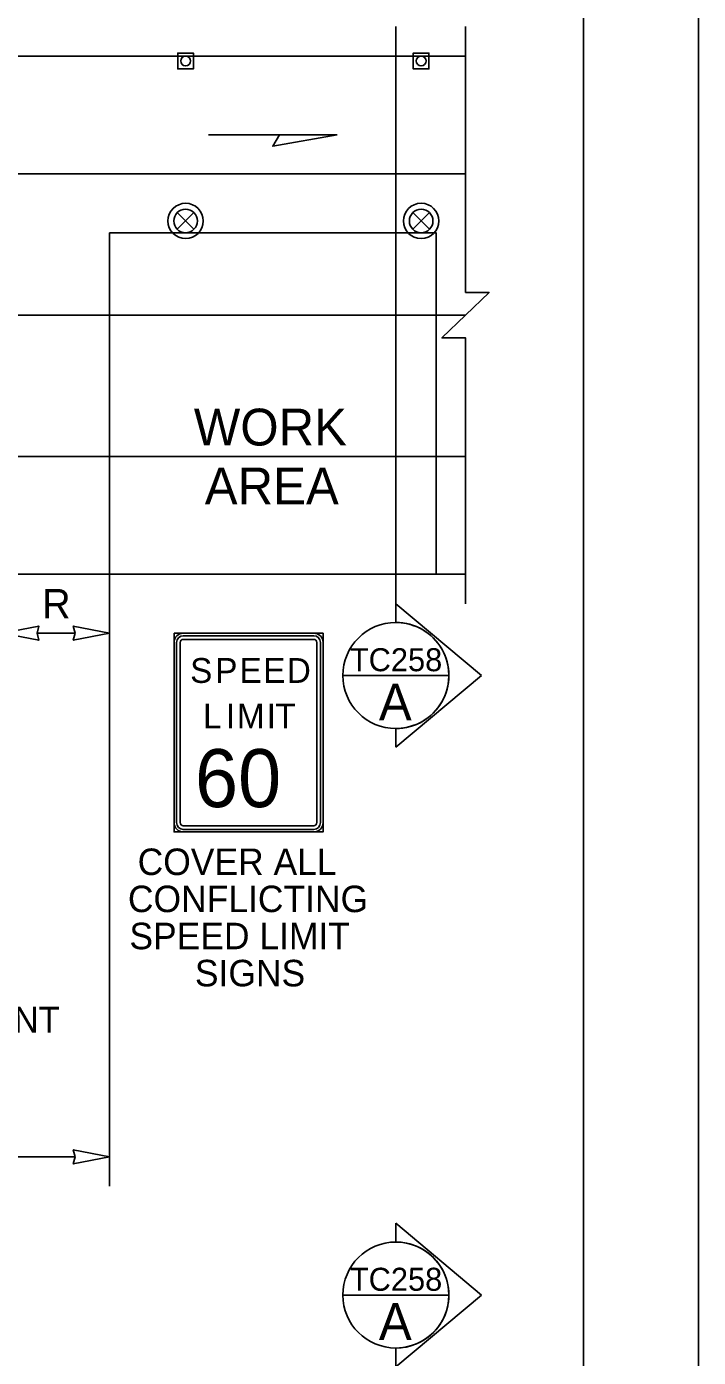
# Model space of a CAD drawing. Extents: x 99999 to 100116, y 99995 to 100013.
# Drawn here: x 100054.238 to 100056.062, y 100004.663 to 100008.279 of the extents above; entities that cross this region are included whole.
import ezdxf

# ---------------------------------------------------------------- set-up
doc = ezdxf.new("R2010")
doc.units = 0
for name, color, linetype in [('RD_MK_LineEdgeYellow', 7, 'Continuous'), ('RD_MK_LineLane', 7, 'Continuous'), ('SH_GI_PlotLimits', 7, 'Continuous'), ('SH_GI_SectionCut', 7, 'Continuous'), ('SH_GI_SheetBorder', 7, 'Continuous'), ('TR_SN_ConstructionSigns', 7, 'Continuous'), ('TR_WZ_TrafficCone', 7, 'Continuous'), ('TR_WZ_TrafficSafetyDrum', 7, 'Continuous'), ('TR_WZ_WorkAreaLabel', 7, 'Continuous'), ('TR_WZ_WorkZoneDetails', 7, 'Continuous'), ('TR_WZ_WorkZoneTextCurrent', 7, 'Continuous')]:
    doc.layers.add(name, color=color, linetype=linetype)

msp = doc.modelspace()

# ---------------------------------------------------------------- linework, layer by layer
at = {"layer": 'RD_MK_LineEdgeYellow'}
for p, q in [((100048.195, 100007.8789), (100055.43, 100007.8789)), ((100052.7368, 100007.1109), (100055.43, 100007.1109))]:
    msp.add_line(p, q, dxfattribs=at)
at = {"layer": 'RD_MK_LineLane'}
msp.add_lwpolyline([(100055.43, 100007.4949), (100048.195, 100007.4949)], dxfattribs=at)
at = {"layer": 'SH_GI_PlotLimits'}
msp.add_lwpolyline([(100039.0625, 99999.6875), (100056.0625, 99999.6875), (100056.0625, 100010.6875), (100039.0625, 100010.6875)], close=True, dxfattribs=at)
at = {"layer": 'SH_GI_SectionCut'}
for p, q in [((100055.2407, 100006.7109), (100055.2407, 100008.2789)), ((100055.2407, 100006.7109), (100055.2407, 100006.66)), ((100055.4733, 100006.516), (100055.2407, 100006.7109)), ((100055.2407, 100006.3211), (100055.4733, 100006.516)), ((100055.2407, 100006.372), (100055.2407, 100006.3211)), ((100055.2407, 100004.9768), (100055.2407, 100005.0277)), ((100055.2407, 100005.0277), (100055.4733, 100004.8328)), ((100055.4733, 100004.8328), (100055.2407, 100004.638)), ((100055.2407, 100004.638), (100055.2407, 100004.6888))]:
    msp.add_line(p, q, dxfattribs=at)
for points in [[(100055.0967, 100006.516), (100055.3847, 100006.516)], [(100055.0967, 100004.8328), (100055.3847, 100004.8328)]]:
    msp.add_lwpolyline(points, dxfattribs=at)
for centre in [(100055.2407, 100006.516), (100055.2407, 100004.8328)]:
    msp.add_circle(centre, 0.144, dxfattribs=at)
for centre in [(100055.2407, 100006.516), (100055.2407, 100004.8328)]:
    msp.add_arc(centre, 0.144, 269.9978, 90.0022, dxfattribs=at)
at = {"layer": 'SH_GI_SheetBorder'}
msp.add_line((100055.75, 100010.375), (100055.75, 100000), dxfattribs=at)
at = {"layer": 'TR_SN_ConstructionSigns'}
for p, q in [((100054.6633, 100006.6309), (100055.0177, 100006.6309)), ((100055.0177, 100006.6309), (100054.6633, 100006.6309)), ((100055.0177, 100006.6239), (100054.6633, 100006.6239)), ((100054.6633, 100006.614), (100055.0177, 100006.614)), ((100054.638, 100006.1162), (100054.638, 100006.6056)), ((100054.638, 100006.6056), (100054.638, 100006.1162)), ((100054.6451, 100006.6056), (100054.6451, 100006.1162)), ((100054.6549, 100006.1162), (100054.6549, 100006.6056)), ((100055.0261, 100006.6056), (100055.0261, 100006.1162)), ((100055.036, 100006.1162), (100055.036, 100006.6056)), ((100055.043, 100006.6056), (100055.043, 100006.1162)), ((100055.043, 100006.1162), (100055.043, 100006.6056)), ((100055.0177, 100006.1078), (100054.6633, 100006.1078)), ((100054.6633, 100006.0979), (100055.0177, 100006.0979)), ((100055.0177, 100006.0909), (100054.6633, 100006.0909)), ((100054.6633, 100006.0909), (100055.0177, 100006.0909))]:
    msp.add_line(p, q, dxfattribs=at)
msp.add_lwpolyline([(100054.638, 100006.6309), (100055.043, 100006.6309), (100055.043, 100006.0909), (100054.638, 100006.0909)], close=True, dxfattribs=at)
for centre, radius, start, end in [((100054.6633, 100006.6056), 0.0253, 90, 180), ((100054.6633, 100006.6056), 0.0253, 90, 180), ((100054.6633, 100006.6056), 0.0183, 90, 180), ((100054.6633, 100006.6056), 0.00844, 90, 180), ((100055.0177, 100006.6056), 0.0253, 0, 90), ((100055.0177, 100006.6056), 0.0253, 360, 90), ((100055.0177, 100006.6056), 0.0183, 0, 90), ((100055.0177, 100006.6056), 0.00844, 360, 90), ((100054.6633, 100006.1162), 0.0253, 180, 270), ((100054.6633, 100006.1162), 0.0253, 180, 270), ((100054.6633, 100006.1162), 0.0183, 180, 270), ((100054.6633, 100006.1162), 0.00844, 180, 270), ((100055.0177, 100006.1162), 0.0253, 270, 0), ((100055.0177, 100006.1162), 0.0183, 270, 360), ((100055.0177, 100006.1162), 0.00844, 270, 0), ((100055.0177, 100006.1162), 0.0253, 270, 0)]:
    msp.add_arc(centre, radius, start, end, dxfattribs=at)
at = {"layer": 'TR_WZ_TrafficCone'}
for points in [[(100054.6481, 100008.2069), (100054.6907, 100008.2069), (100054.6907, 100008.1642), (100054.6481, 100008.1642), (100054.6481, 100008.2069)], [(100054.6481, 100008.1642), (100054.6907, 100008.1642), (100054.6907, 100008.2069), (100054.6481, 100008.2069), (100054.6481, 100008.1642)], [(100055.2881, 100008.2069), (100055.3307, 100008.2069), (100055.3307, 100008.1642), (100055.2881, 100008.1642), (100055.2881, 100008.2069)], [(100055.2881, 100008.1642), (100055.3307, 100008.1642), (100055.3307, 100008.2069), (100055.2881, 100008.2069), (100055.2881, 100008.1642)]]:
    msp.add_lwpolyline(points, dxfattribs=at)
for centre in [(100054.6694, 100008.1856), (100055.3094, 100008.1856)]:
    msp.add_circle(centre, 0.0133, dxfattribs=at)
at = {"layer": 'TR_WZ_TrafficSafetyDrum'}
for p, q in [((100054.6468, 100007.7735), (100054.692, 100007.7283)), ((100054.692, 100007.7735), (100054.6468, 100007.7283)), ((100055.2868, 100007.7735), (100055.332, 100007.7283)), ((100055.332, 100007.7735), (100055.2868, 100007.7283))]:
    msp.add_line(p, q, dxfattribs=at)
for centre, radius in [((100054.6694, 100007.7509), 0.048), ((100054.6694, 100007.7509), 0.048), ((100054.6694, 100007.7509), 0.032), ((100055.3094, 100007.7509), 0.048), ((100055.3094, 100007.7509), 0.048), ((100055.3094, 100007.7509), 0.032)]:
    msp.add_circle(centre, radius, dxfattribs=at)
at = {"layer": 'TR_WZ_WorkZoneDetails'}
for p, q in [((100048.195, 100008.1989), (100055.43, 100008.1989)), ((100054.9242, 100007.985), (100054.7313, 100007.985)), ((100052.7368, 100006.7909), (100055.43, 100006.7909)), ((100054.4628, 100006.7909), (100054.4628, 100005.1282)), ((100054.3691, 100006.6309), (100054.2662, 100006.6309)), ((100054.3691, 100006.6309), (100054.2662, 100006.6309)), ((100054.3691, 100005.2082), (100050.6962, 100005.2082))]:
    msp.add_line(p, q, dxfattribs=at)
msp.add_lwpolyline([(100055.43, 100006.7109), (100055.43, 100007.433), (100055.366, 100007.433), (100055.494, 100007.5569), (100055.43, 100007.5569), (100055.43, 100008.2789)], dxfattribs=at)
for points in [[(100055.0815, 100007.985), (100054.9064, 100007.9541), (100054.9242, 100007.985)], [(100054.4628, 100007.7189), (100054.4628, 100006.7909), (100055.35, 100006.7909), (100055.35, 100007.7189)], [(100054.1724, 100006.6309), (100054.2707, 100006.6502), (100054.2662, 100006.6309), (100054.2707, 100006.6116)], [(100054.4628, 100006.6309), (100054.3645, 100006.6502), (100054.3691, 100006.6309), (100054.3645, 100006.6116)], [(100054.4628, 100005.2082), (100054.3645, 100005.2275), (100054.3691, 100005.2082), (100054.3645, 100005.1889)]]:
    msp.add_lwpolyline(points, close=True, dxfattribs=at)

# ---------------------------------------------------------------- texts
at = {"layer": 'SH_GI_SectionCut'}
for p in [(100055.1158, 100006.5276), (100055.1158, 100004.8444)]:
    msp.add_text('TC258', height=0.0625, dxfattribs=at).set_placement(p)
for p in [(100055.1945, 100006.394), (100055.1945, 100004.7108)]:
    msp.add_text('A', height=0.1, rotation=359.99, dxfattribs=at).set_placement(p)
at = {"layer": 'TR_SN_ConstructionSigns'}
for s, height, p in [('S', 0.0675, (100054.6819, 100006.4959)), ('P', 0.0675, (100054.7501, 100006.4959)), ('E', 0.0675, (100054.8162, 100006.4959)), ('E', 0.0675, (100054.8803, 100006.4959)), ('D', 0.0675, (100054.9445, 100006.4959)), ('L', 0.0675, (100054.717, 100006.3722)), ('I', 0.0675, (100054.7791, 100006.3722)), ('M', 0.0675, (100054.8088, 100006.3722)), ('I', 0.0675, (100054.8898, 100006.3722)), ('T', 0.0675, (100054.9134, 100006.3722)), ('60', 0.1575, (100054.6949, 100006.1584)), ('COVER ALL', 0.072, (100054.5392, 100005.9739)), ('CONFLICTING', 0.072, (100054.5128, 100005.8731)), ('SPEED LIMIT', 0.072, (100054.5168, 100005.7723)), ('SIGNS', 0.072, (100054.6947, 100005.6715))]:
    msp.add_text(s, height=height, dxfattribs=at).set_placement(p)
at = {"layer": 'TR_WZ_WorkAreaLabel'}
for s, p in [('WORK', (100054.6919, 100007.1409)), ('AREA', (100054.7215, 100006.9809))]:
    msp.add_text(s, height=0.1, dxfattribs=at).set_placement(p)
at = {"layer": 'TR_WZ_WorkZoneDetails'}
msp.add_text('STRIPS PRESENT', height=0.07, dxfattribs=at).set_placement((100053.5214, 100005.546))
at = {"layer": 'TR_WZ_WorkZoneTextCurrent'}
msp.add_text('R', height=0.08, dxfattribs=at).set_placement((100054.28, 100006.6709))
msp.add_text('R', height=0.08, dxfattribs=at).set_placement((100054.28, 100006.6709))

doc.saveas('drawing.dxf')
